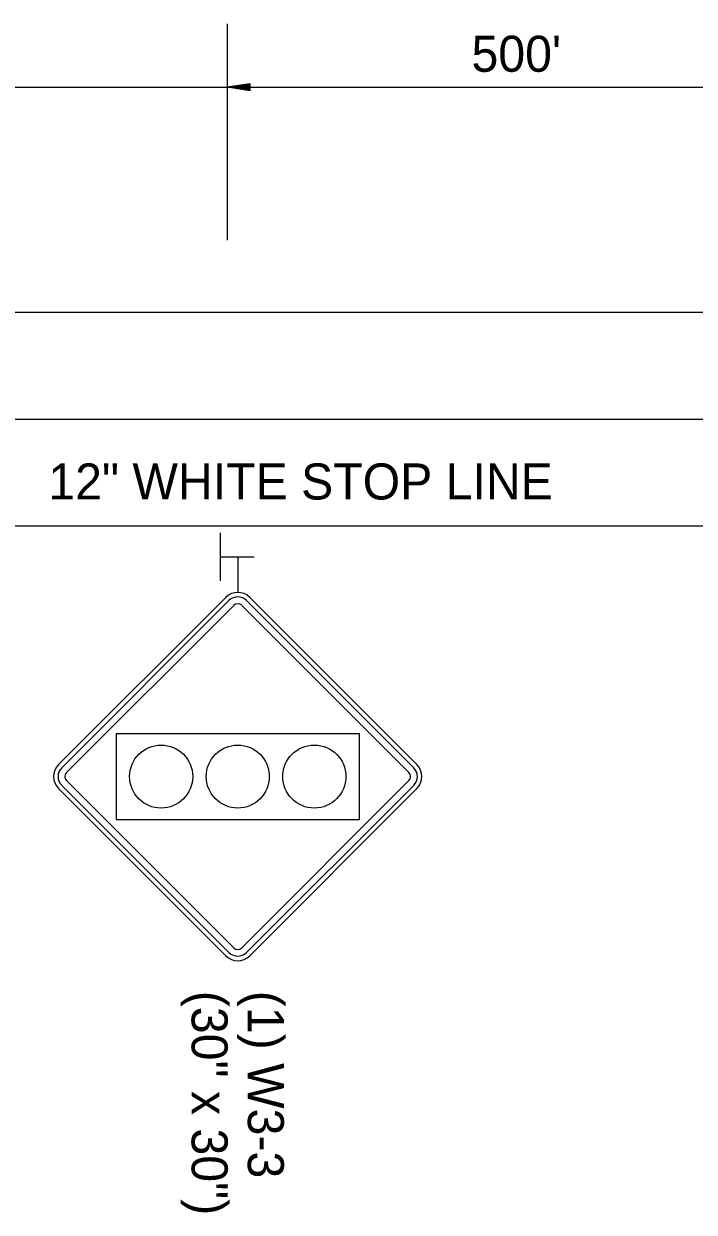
# Model space of a CAD drawing. Extents: x 1930579 to 1934718, y 596452 to 597844.
# Drawn here: x 1932933.5 to 1933045.1, y 597281.7 to 597479.5 of the extents above; entities that cross this region are included whole.
import ezdxf

# ---------------------------------------------------------------- set-up
doc = ezdxf.new("R2010")
doc.units = 0
for name, color, linetype in [('Default', 7, 'Continuous'), ('P_TC_Signs_Permanent', 7, 'Continuous'), ('R_Annotation', 7, 'Continuous')]:
    doc.layers.add(name, color=color, linetype=linetype)

msp = doc.modelspace()

# ---------------------------------------------------------------- linework, layer by layer
at = {"layer": 'Default'}
for p, q in [((1932967.38, 597479.5), (1932967.38, 597443.47)), ((1932868.48, 597468.94), (1932968.23, 597468.94)), ((1932971.21, 597469.52), (1932967.38, 597468.94)), ((1932967.38, 597468.94), (1933068.51, 597468.94)), ((1932971.21, 597468.36), (1932967.38, 597468.94)), ((1932971.21, 597469.42), (1932968.02, 597468.94)), ((1932971.21, 597468.46), (1932968.02, 597468.94)), ((1932971.21, 597469.32), (1932968.68, 597468.94)), ((1932971.21, 597468.56), (1932968.68, 597468.94)), ((1932971.21, 597469.23), (1932969.32, 597468.94)), ((1932971.21, 597468.65), (1932969.32, 597468.94)), ((1932971.21, 597469.13), (1932969.97, 597468.94)), ((1932971.21, 597468.75), (1932969.97, 597468.94)), ((1932971.21, 597469.03), (1932970.61, 597468.94)), ((1932971.21, 597468.85), (1932970.61, 597468.94)), ((1932971.21, 597468.36), (1932971.21, 597469.52)), ((1932535.52, 597431.5), (1933637.52, 597431.5)), ((1932443.39, 597413.71), (1933637.52, 597413.71)), ((1932535.52, 597395.93), (1933637.52, 597395.93)), ((1932966.27, 597386.79), (1932966.27, 597394.79)), ((1932966.38, 597390.77), (1932971.85, 597390.77))]:
    msp.add_line(p, q, dxfattribs=at)
at = {"layer": 'P_TC_Signs_Permanent'}
for p, q in [((1932939.29, 597356.19), (1932967.13, 597384.03)), ((1932939.82, 597355.66), (1932967.66, 597383.5)), ((1932970.58, 597383.5), (1932998.42, 597355.66)), ((1932971.11, 597384.03), (1932998.95, 597356.19)), ((1932968.45, 597382.7), (1932940.61, 597354.86)), ((1932997.62, 597354.86), (1932969.78, 597382.7)), ((1932967.13, 597324.37), (1932939.29, 597352.21)), ((1932967.66, 597324.9), (1932939.82, 597352.74)), ((1932940.61, 597353.54), (1932968.45, 597325.69)), ((1932969.78, 597325.69), (1932997.62, 597353.54)), ((1932998.42, 597352.74), (1932970.58, 597324.9)), ((1932998.95, 597352.21), (1932971.11, 597324.37))]:
    msp.add_line(p, q, dxfattribs=at)
msp.add_lwpolyline([(1932948.87, 597361.32), (1932948.87, 597347.07), (1932989.37, 597347.07), (1932989.37, 597361.32)], close=True, dxfattribs=at)
for centre in [(1932956.37, 597354.2), (1932969.12, 597354.2), (1932981.87, 597354.2)]:
    msp.add_circle(centre, 5.25, dxfattribs=at)
for centre, radius, start, end in [((1932969.12, 597382.04), 2.81, 45, 135), ((1932969.12, 597382.04), 2.06, 45, 135), ((1932969.12, 597382.04), 0.938, 45, 135), ((1932941.27, 597354.2), 2.81, 135, 225), ((1932996.96, 597354.2), 2.81, 315, 45), ((1932941.27, 597354.2), 2.06, 135, 225), ((1932941.27, 597354.2), 0.938, 135, 225), ((1932996.96, 597354.2), 0.938, 315, 45), ((1932996.96, 597354.2), 2.06, 315, 45), ((1932969.12, 597326.36), 2.81, 225, 315), ((1932969.12, 597326.36), 2.06, 225, 315), ((1932969.12, 597326.36), 0.938, 225, 315)]:
    msp.add_arc(centre, radius, start, end, dxfattribs=at)
at = {"layer": 'R_Annotation'}
msp.add_line((1932969.12, 597390.77), (1932969.12, 597384.85), dxfattribs=at)

# ---------------------------------------------------------------- texts
at = {"layer": 'Default'}
for s, height, p in [("500'", 6, (1933008.04, 597471.51)), ('12" WHITE STOP LINE', 5.9996, (1932937.59, 597400.32))]:
    msp.add_text(s, height=height, rotation=360, dxfattribs=at).set_placement(p)
at = {"layer": 'R_Annotation'}
for s, height, p in [('(30" x 30")', 5.9996, (1932961.44, 597318.54)), ('(1) W3-3', 6, (1932970.8, 597318.54))]:
    msp.add_text(s, height=height, rotation=270, dxfattribs=at).set_placement(p)

doc.saveas('drawing.dxf')
